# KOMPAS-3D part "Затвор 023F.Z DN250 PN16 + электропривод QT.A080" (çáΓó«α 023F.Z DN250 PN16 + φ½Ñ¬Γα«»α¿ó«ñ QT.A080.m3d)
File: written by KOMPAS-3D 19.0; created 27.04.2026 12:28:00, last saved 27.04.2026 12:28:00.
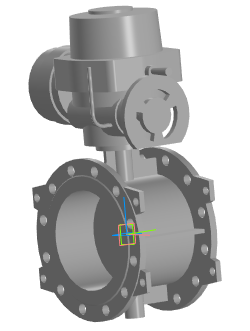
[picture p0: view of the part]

Document properties: Полное имя файла: Затвор 023F.Z DN250 PN16 + электропривод QT.A080.a3d

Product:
- Part/product: Затвор 023F.Z DN250 PN16 + электропривод QT.A080
    Масса: 199.301

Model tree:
1. Операция без истории:1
